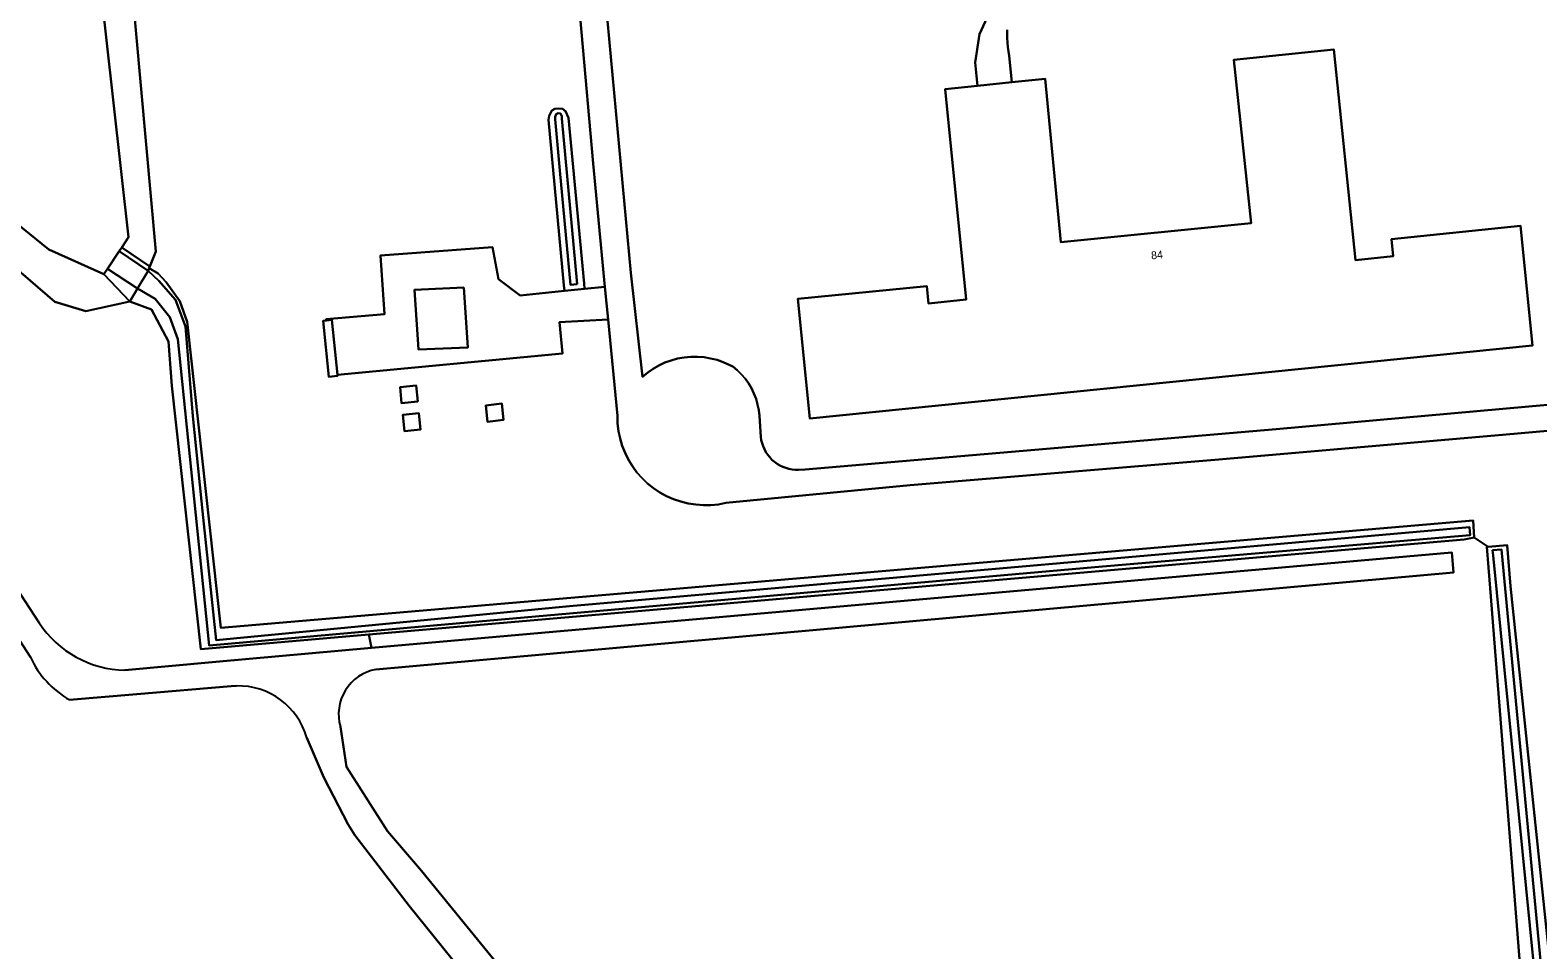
# Model space of a CAD drawing. Extents: x 158132 to 159664, y 385256 to 387218.
# Drawn here: x 158367.1 to 158558.9, y 386531.1 to 386648.1 of the extents above; entities that cross this region are included whole.
import ezdxf

# ---------------------------------------------------------------- set-up
doc = ezdxf.new("R2010")
doc.units = 0
for name, color, linetype in [('IMGEO_Gemengd_bos', 7, 'Continuous'), ('IMGEO_Groenvoorziening', 7, 'Continuous'), ('IMGEO_Meer_plas_ven_vijver', 7, 'Continuous'), ('IMGEO_Oever', 7, 'Continuous'), ('IMGEO_Pand', 7, 'Continuous'), ('IMGEO_Pand_nummerreeks', 7, 'Continuous'), ('IMGEO_Rijbaan_lokaal_gesloten', 7, 'Continuous'), ('IMGEO_Voetpad_onverhard', 7, 'Continuous'), ('IMGEO_Voetpad_open', 7, 'Continuous'), ('IMGEO_Waterloop', 7, 'Continuous')]:
    doc.layers.add(name, color=color, linetype=linetype)

msp = doc.modelspace()

# ---------------------------------------------------------------- linework, layer by layer
at = {"layer": 'IMGEO_Gemengd_bos'}
for points in [[(158367.16, 386568.36), (158343.96, 386604.24), (158325.11, 386633.29), (158316.42, 386645.99)], [(158710.5, 386585.82), (158694.75, 386594.73), (158699.27, 386534.87), (158699.52, 386531.69), (158557.25, 386520.85), (158552.81, 386577.12)], [(158552.81, 386577.12), (158552.39, 386582.4), (158552.53, 386582.41), (158550.77, 386583.59), (158549.48, 386583.35), (158410.22, 386571.24), (158410.52, 386569.56), (158547.92, 386581.66), (158548.14, 386579.12), (158411.08, 386566.81)], [(158393.38, 386564.72), (158392.7, 386564.67), (158380.71, 386563.64), (158372.15, 386562.92)], [(158406.58, 386559.5), (158407.36, 386554.43), (158412.58, 386546.23), (158416.91, 386541.17), (158442.58, 386509.71), (158448.36, 386503.02), (158452.61, 386500), (158453.96, 386499.04), (158456.49, 386498.14), (158462.82, 386498.14), (158466.25, 386498.5), (158477.43, 386500), (158500, 386502.83), (158738.6, 386532.78), (158740.9, 386533.67)], [(158437.5, 386509.93), (158425.02, 386524.68), (158415.31, 386536.74), (158408.44, 386545.73), (158407.57, 386547.08), (158404.48, 386553.07), (158402.3, 386558.12)]]:
    msp.add_lwpolyline(points, dxfattribs=at)
for centre, radius, start, end in [((158378.32, 386573.6), 12.33, 205.1773, 240.0142), ((158412.17, 386561.1), 5.81, 100.7575, 195.9803), ((158393.61, 386555.69), 9.02, 15.6029, 91.463)]:
    msp.add_arc(centre, radius, start, end, dxfattribs=at)
at = {"layer": 'IMGEO_Groenvoorziening'}
for points in [[(158378.05, 386675.83), (158383.11, 386619.97), (158382.35, 386618.04), (158382.28, 386617.86), (158383.41, 386617.14), (158384.42, 386616.07), (158386.16, 386613.65), (158387.09, 386611.03), (158391.36, 386572.1), (158550.62, 386585.75), (158550.77, 386583.59), (158552.53, 386582.41), (158554.97, 386582.61), (158555.4, 386577.39), (158560.93, 386524.32)], [(158594.96, 386600.25), (158554.82, 386596.68), (158518.31, 386593.52), (158479.06, 386590.22), (158455.62, 386587.98), (158454.67, 386587.8), (158453.71, 386587.71), (158452.74, 386587.69), (158451.77, 386587.76), (158450.81, 386587.91), (158449.87, 386588.15), (158448.95, 386588.46), (158448.06, 386588.85), (158447.21, 386589.32), (158446.41, 386589.86), (158445.65, 386590.47), (158444.95, 386591.14), (158444.3, 386591.86), (158443.73, 386592.64), (158443.22, 386593.47), (158442.79, 386594.34), (158442.43, 386595.24), (158442.15, 386596.17), (158441.95, 386597.12), (158441.84, 386598.08), (158441.81, 386599.05), (158440.63, 386611.3), (158434.44, 386610.98), (158434.82, 386606.97), (158406.21, 386604.28), (158406.22, 386604.13), (158405.13, 386604.02), (158404.41, 386611.16), (158404.8, 386611.2), (158404.79, 386611.37), (158412.2, 386612), (158411.7, 386619.44), (158425.93, 386620.49), (158426.69, 386616.44), (158429.43, 386614.38), (158435.07, 386614.95), (158435, 386615.66), (158433.04, 386636.71), (158433.13, 386637.23), (158433.46, 386637.9), (158433.86, 386638.11), (158434.32, 386638.16), (158434.84, 386638.1), (158435.2, 386637.8), (158435.61, 386636.95), (158437.57, 386615.9), (158437.64, 386615.22), (158440.23, 386615.48), (158438.72, 386631.16), (158435.76, 386664.58)], [(158439.91, 386656.2), (158443.51, 386617.24), (158445.01, 386604.01), (158445.66, 386604.55), (158446.35, 386605.04), (158447.09, 386605.46), (158447.85, 386605.82), (158448.65, 386606.11), (158449.46, 386606.33), (158450.3, 386606.48), (158451.14, 386606.56), (158451.98, 386606.57), (158452.83, 386606.51), (158453.66, 386606.37), (158454.48, 386606.17), (158455.28, 386605.89), (158456.47, 386605.34), (158457.04, 386604.87), (158457.57, 386604.36), (158458.05, 386603.8), (158458.48, 386603.2), (158458.85, 386602.57), (158459.18, 386601.91), (158459.44, 386601.22), (158459.64, 386600.52), (158459.78, 386599.79), (158459.86, 386599.06), (158460.05, 386596.39), (158460.11, 386595.98), (158460.21, 386595.58), (158460.33, 386595.19), (158460.5, 386594.81), (158460.7, 386594.45), (158460.92, 386594.1), (158461.18, 386593.78), (158461.47, 386593.48), (158461.78, 386593.21), (158462.11, 386592.97), (158462.46, 386592.76), (158462.83, 386592.58), (158463.22, 386592.43), (158463.62, 386592.32), (158464.02, 386592.24), (158464.43, 386592.2), (158464.85, 386592.2), (158465.67, 386592.24), (158525.58, 386597.37), (158602.14, 386604.25)], [(158491.39, 386648.17), (158491.39, 386647.12), (158491.46, 386645.94), (158491.61, 386644.85), (158491.95, 386641.48), (158496.21, 386641.91), (158498.22, 386621.13), (158522.4, 386623.58), (158520.2, 386644.34), (158532.92, 386645.63), (158535.67, 386618.86), (158540.45, 386619.35), (158540.23, 386621.53), (158556.65, 386623.24), (158558.2, 386608.01), (158466.28, 386598.7), (158464.74, 386613.93), (158481.17, 386615.54), (158481.39, 386613.36), (158486.17, 386613.85), (158483.5, 386640.62), (158487.61, 386641.04), (158487.31, 386644.01), (158487.86, 386647.61), (158489.3, 386650.75)], [(158319.99, 386646.08), (158327.38, 386635.02), (158346.5, 386606.14), (158368.27, 386572.72)], [(158379.18, 386566.7), (158390.75, 386567.78), (158410.52, 386569.56), (158410.22, 386571.24), (158388.85, 386569.38), (158385.15, 386602.86), (158384.73, 386608.52), (158382.57, 386612.59), (158379.82, 386613.61), (158374.22, 386612.37), (158370.26, 386613.55), (158360.63, 386621.82)]]:
    msp.add_lwpolyline(points, dxfattribs=at)
for points in [[(158416.42, 386600.88), (158414.37, 386600.67), (158414.17, 386602.71), (158416.21, 386602.91)], [(158427.34, 386598.53), (158425.31, 386598.3), (158425.08, 386600.39), (158427.11, 386600.61)], [(158416.77, 386597.32), (158414.72, 386597.11), (158414.52, 386599.2), (158416.56, 386599.4)]]:
    msp.add_lwpolyline(points, close=True, dxfattribs=at)
msp.add_arc((158379.48, 386580.14), 13.44, 213.4985, 268.7308, dxfattribs=at)
at = {"layer": 'IMGEO_Meer_plas_ven_vijver'}
msp.add_lwpolyline([(158359.43, 386628.37), (158369.5, 386620.22), (158376.5, 386617.07), (158376.97, 386617.77), (158378.44, 386619.98), (158378.77, 386620.48), (158379.64, 386621.79), (158373, 386681.42), (158375.01, 386691.77), (158381.5, 386698.64), (158392.78, 386704.05), (158393.01, 386707.37), (158391.45, 386709.51), (158387.29, 386715.35), (158382.05, 386717.05), (158370.47, 386713.08), (158358.29, 386705.89)], dxfattribs=at)
at = {"layer": 'IMGEO_Oever'}
msp.add_lwpolyline([(158373, 386681.42), (158379.64, 386621.79), (158378.77, 386620.48), (158382.35, 386618.04), (158383.11, 386619.97), (158378.05, 386675.83)], dxfattribs=at)
for points in [[(158348.56, 386640.72), (158345.74, 386638.78), (158360.63, 386621.82), (158370.26, 386613.55), (158374.22, 386612.37), (158379.82, 386613.61), (158376.5, 386617.07), (158369.5, 386620.22), (158359.43, 386628.37), (158348.69, 386640.55)], [(158435.07, 386614.95), (158437.64, 386615.22), (158437.57, 386615.9), (158435.61, 386636.95), (158435.2, 386637.8), (158434.84, 386638.1), (158434.32, 386638.16), (158433.86, 386638.11), (158433.46, 386637.9), (158433.13, 386637.23), (158433.04, 386636.71), (158435, 386615.66)], [(158436.71, 386615.82), (158435.84, 386615.74), (158434.49, 386630.28), (158433.88, 386636.79), (158433.9, 386637.09), (158434.04, 386637.42), (158434.28, 386637.56), (158434.58, 386637.5), (158434.73, 386637.15), (158434.75, 386636.87)], [(158378.77, 386620.48), (158378.44, 386619.98), (158382.14, 386617.49), (158382.28, 386617.86), (158382.35, 386618.04)], [(158376.97, 386617.77), (158376.5, 386617.07), (158379.82, 386613.61), (158380.8, 386615.25)], [(158380.8, 386615.25), (158379.82, 386613.61), (158382.57, 386612.59), (158384.73, 386608.52), (158385.15, 386602.86), (158388.85, 386569.38), (158410.22, 386571.24), (158549.48, 386583.35), (158550.77, 386583.59), (158550.62, 386585.75), (158391.36, 386572.1), (158387.09, 386611.03), (158386.16, 386613.65), (158384.42, 386616.07), (158383.41, 386617.14), (158382.28, 386617.86), (158382.14, 386617.49), (158383.5, 386616.22), (158385.6, 386613.8), (158386.88, 386610.4), (158387.82, 386599.03), (158389.13, 386586.13), (158390.8, 386570.54), (158435.73, 386574.83), (158483.15, 386579), (158526.62, 386582.82), (158550.17, 386584.88), (158550.26, 386583.88), (158502.54, 386579.82), (158416.98, 386572.27), (158389.89, 386569.83), (158385.92, 386608.82), (158384.88, 386611.6), (158383.04, 386613.94)], [(158699.52, 386531.69), (158699.27, 386534.87), (158560.93, 386524.32), (158555.4, 386577.39), (158554.97, 386582.61), (158552.53, 386582.41), (158552.39, 386582.4), (158552.81, 386577.12), (158557.25, 386520.85)], [(158553.1, 386581.98), (158554.24, 386582.06), (158554.54, 386578.89), (158559.85, 386523.08), (158621.58, 386527.43), (158638, 386528.76), (158675.25, 386531.75), (158698.53, 386533.91), (158698.65, 386532.63), (158664.15, 386529.97), (158634.37, 386527.66), (158583.72, 386523.55), (158559.05, 386521.76), (158558.32, 386529.53), (158553.17, 386581.3)]]:
    msp.add_lwpolyline(points, close=True, dxfattribs=at)
at = {"layer": 'IMGEO_Pand'}
for points in [[(158556.65, 386623.24), (158540.23, 386621.53), (158540.45, 386619.35), (158535.67, 386618.86), (158532.92, 386645.63), (158520.2, 386644.34), (158522.4, 386623.58), (158498.22, 386621.13), (158496.21, 386641.91), (158491.95, 386641.48), (158487.61, 386641.04), (158483.5, 386640.62), (158486.17, 386613.85), (158481.39, 386613.36), (158481.17, 386615.54), (158464.74, 386613.93), (158466.28, 386598.7), (158558.2, 386608.01)], [(158422.28, 386615.36), (158415.99, 386615.08), (158416.5, 386607.48), (158422.78, 386607.76)], [(158404.8, 386611.2), (158404.41, 386611.16), (158405.13, 386604.02), (158406.22, 386604.13), (158406.21, 386604.28), (158405.51, 386611.27)], [(158416.42, 386600.88), (158416.21, 386602.91), (158414.17, 386602.71), (158414.37, 386600.67)], [(158425.31, 386598.3), (158427.34, 386598.53), (158427.11, 386600.61), (158425.08, 386600.39)], [(158414.52, 386599.2), (158414.72, 386597.11), (158416.77, 386597.32), (158416.56, 386599.4)]]:
    msp.add_lwpolyline(points, close=True, dxfattribs=at)
at = {"layer": 'IMGEO_Rijbaan_lokaal_gesloten'}
for points in [[(158435.76, 386664.58), (158438.72, 386631.16), (158440.23, 386615.48), (158440.63, 386611.3), (158441.81, 386599.05), (158441.84, 386598.08), (158441.95, 386597.12), (158442.15, 386596.17), (158442.43, 386595.24), (158442.79, 386594.34), (158443.22, 386593.47), (158443.73, 386592.64), (158444.3, 386591.86), (158444.95, 386591.14), (158445.65, 386590.47), (158446.41, 386589.86), (158447.21, 386589.32), (158448.06, 386588.85), (158448.95, 386588.46), (158449.87, 386588.15), (158450.81, 386587.91), (158451.77, 386587.76), (158452.74, 386587.69), (158453.71, 386587.71), (158454.67, 386587.8), (158455.62, 386587.98), (158479.06, 386590.22), (158518.31, 386593.52), (158554.82, 386596.68), (158594.96, 386600.25)], [(158602.14, 386604.25), (158525.58, 386597.37), (158465.67, 386592.24), (158464.85, 386592.2), (158464.43, 386592.2), (158464.02, 386592.24), (158463.62, 386592.32), (158463.22, 386592.43), (158462.83, 386592.58), (158462.46, 386592.76), (158462.11, 386592.97), (158461.78, 386593.21), (158461.47, 386593.48), (158461.18, 386593.78), (158460.92, 386594.1), (158460.7, 386594.45), (158460.5, 386594.81), (158460.33, 386595.19), (158460.21, 386595.58), (158460.11, 386595.98), (158460.05, 386596.39), (158459.86, 386599.06), (158459.78, 386599.79), (158459.64, 386600.52), (158459.44, 386601.22), (158459.18, 386601.91), (158458.85, 386602.57), (158458.48, 386603.2), (158458.05, 386603.8), (158457.57, 386604.36), (158457.04, 386604.87), (158456.47, 386605.34), (158455.28, 386605.89), (158454.48, 386606.17), (158453.66, 386606.37), (158452.83, 386606.51), (158451.98, 386606.57), (158451.14, 386606.56), (158450.3, 386606.48), (158449.46, 386606.33), (158448.65, 386606.11), (158447.85, 386605.82), (158447.09, 386605.46), (158446.35, 386605.04), (158445.66, 386604.55), (158445.01, 386604.01), (158443.51, 386617.24), (158439.91, 386656.2)], [(158368.27, 386572.72), (158346.5, 386606.14), (158327.38, 386635.02), (158319.99, 386646.08), (158316.42, 386645.99), (158325.11, 386633.29), (158343.96, 386604.24), (158367.16, 386568.36)], [(158411.08, 386566.81), (158548.14, 386579.12), (158547.92, 386581.66), (158410.52, 386569.56), (158390.75, 386567.78), (158379.18, 386566.7)], [(158372.15, 386562.92), (158380.71, 386563.64), (158392.7, 386564.67), (158393.38, 386564.72)], [(158740.9, 386533.67), (158738.6, 386532.78), (158500, 386502.83), (158477.43, 386500), (158466.25, 386498.5), (158462.82, 386498.14), (158456.49, 386498.14), (158453.96, 386499.04), (158452.61, 386500), (158448.36, 386503.02), (158442.58, 386509.71), (158416.91, 386541.17), (158412.58, 386546.23), (158407.36, 386554.43), (158406.58, 386559.5)], [(158402.3, 386558.12), (158404.48, 386553.07), (158407.57, 386547.08), (158408.44, 386545.73), (158415.31, 386536.74), (158425.02, 386524.68), (158437.5, 386509.93), (158445.8, 386499.5), (158448.86, 386495.84), (158467.36, 386474.71), (158468.36, 386475.55), (158469.79, 386476.77), (158466.76, 386480.47), (158461.58, 386486.69)]]:
    msp.add_lwpolyline(points, dxfattribs=at)
for centre, radius, start, end in [((158379.48, 386580.14), 13.44, 213.4985, 268.7308), ((158378.32, 386573.6), 12.33, 205.1773, 240.0142), ((158412.17, 386561.1), 5.81, 100.7575, 195.9803), ((158393.61, 386555.69), 9.02, 15.6029, 91.463)]:
    msp.add_arc(centre, radius, start, end, dxfattribs=at)
at = {"layer": 'IMGEO_Voetpad_onverhard'}
msp.add_lwpolyline([(158489.3, 386650.75), (158487.86, 386647.61), (158487.31, 386644.01), (158487.61, 386641.04), (158491.95, 386641.48), (158491.61, 386644.85), (158491.46, 386645.94), (158491.39, 386647.12), (158491.39, 386648.17)], dxfattribs=at)
at = {"layer": 'IMGEO_Voetpad_open'}
for points in [[(158425.93, 386620.49), (158411.7, 386619.44), (158412.2, 386612), (158404.79, 386611.37), (158404.8, 386611.2), (158405.51, 386611.27), (158406.21, 386604.28), (158434.82, 386606.97), (158434.44, 386610.98), (158440.63, 386611.3), (158440.23, 386615.48), (158437.64, 386615.22), (158435.07, 386614.95), (158429.43, 386614.38), (158426.69, 386616.44)], [(158422.28, 386615.36), (158422.78, 386607.76), (158416.5, 386607.48), (158415.99, 386615.08)]]:
    msp.add_lwpolyline(points, close=True, dxfattribs=at)
at = {"layer": 'IMGEO_Waterloop'}
for points in [[(158436.71, 386615.82), (158434.75, 386636.87), (158434.73, 386637.15), (158434.58, 386637.5), (158434.28, 386637.56), (158434.04, 386637.42), (158433.9, 386637.09), (158433.88, 386636.79), (158434.49, 386630.28), (158435.84, 386615.74)], [(158382.14, 386617.49), (158378.44, 386619.98), (158376.97, 386617.77), (158380.8, 386615.25)], [(158382.14, 386617.49), (158380.8, 386615.25), (158383.04, 386613.94), (158384.88, 386611.6), (158385.92, 386608.82), (158389.89, 386569.83), (158416.98, 386572.27), (158502.54, 386579.82), (158550.26, 386583.88), (158550.17, 386584.88), (158526.62, 386582.82), (158483.15, 386579), (158435.73, 386574.83), (158390.8, 386570.54), (158389.13, 386586.13), (158387.82, 386599.03), (158386.88, 386610.4), (158385.6, 386613.8), (158383.5, 386616.22)], [(158553.1, 386581.98), (158553.17, 386581.3), (158558.32, 386529.53), (158559.05, 386521.76), (158583.72, 386523.55), (158634.37, 386527.66), (158664.15, 386529.97), (158698.65, 386532.63), (158698.53, 386533.91), (158675.25, 386531.75), (158638, 386528.76), (158621.58, 386527.43), (158559.85, 386523.08), (158554.54, 386578.89), (158554.24, 386582.06)]]:
    msp.add_lwpolyline(points, close=True, dxfattribs=at)

# ---------------------------------------------------------------- texts
at = {"layer": 'IMGEO_Pand_nummerreeks'}
msp.add_text('84', height=1, rotation=5.5176, dxfattribs=at).set_placement((158509.73, 386618.95))

doc.saveas('drawing.dxf')
